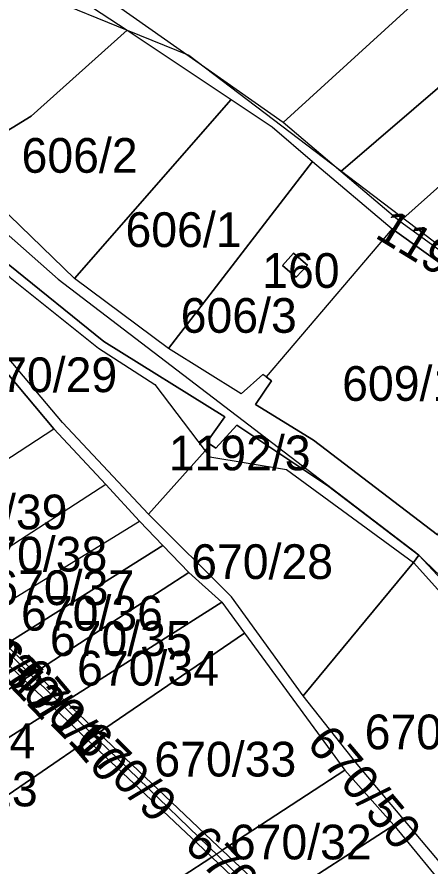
# Model space of a CAD drawing. Extents: x -623250 to -619626, y -1079612 to -1075424.
# Drawn here: x -620248 to -620128.9, y -1076980.5 to -1076735.9 of the extents above; entities that cross this region are included whole.
import ezdxf

# ---------------------------------------------------------------- set-up
doc = ezdxf.new("R2010")
doc.units = 0
for name, color, linetype in [('Cestní síť', 7, 'Continuous'), ('Hranice šetřená (k_ú_Džbánov - vnitřní obvod)', 7, 'Continuous'), ('Parcela nároku', 7, 'Continuous'), ('Parcelní číslo', 7, 'Continuous'), ('Vodní toky', 7, 'Continuous'), ('Železnice', 7, 'Continuous')]:
    doc.layers.add(name, color=color, linetype=linetype)

msp = doc.modelspace()

# ---------------------------------------------------------------- linework, layer by layer
at = {"layer": 'Cestní síť'}
for p, q in [((-620243.09, -1076728.76), (-620216.21, -1076739.68)), ((-620216.21, -1076739.68), (-620198.39, -1076746.92)), ((-620198.39, -1076746.92), (-620118.57, -1076807.57))]:
    msp.add_line(p, q, dxfattribs=at)
at = {"layer": 'Hranice šetřená (k_ú_Džbánov - vnitřní obvod)'}
msp.add_lwpolyline([(-620126.72, -1076885.06), (-620162.51, -1076857.82), (-620179.17, -1076847.51), (-620174.58, -1076840.72), (-620176.18, -1076839.56), (-620177.1, -1076838.89), (-620183.39, -1076844.49), (-620204.25, -1076831.43), (-620231.38, -1076811.27), (-620265.87, -1076777.93), (-620243.92, -1076764.46), (-620216.21, -1076739.68), (-620186.23, -1076759.67), (-620174.43, -1076767.54), (-620162.81, -1076777.54), (-620139.82, -1076796.98), (-620090.81, -1076832)], dxfattribs=at)
at = {"layer": 'Parcela nároku'}
for points in [[(-620218.95, -1076732.82), (-620133.42, -1076663.2), (-620055.39, -1076602.7), (-620048.24, -1076609.49), (-620020.15, -1076639.93), (-620076.81, -1076680.16), (-620171.2, -1076766.27)], [(-620020.15, -1076639.93), (-620003.71, -1076657.74), (-620060.3, -1076699.43), (-620154.59, -1076780.38), (-620171.2, -1076766.27), (-620076.81, -1076680.16)], [(-620339.92, -1076659.27), (-620312.36, -1076646.89), (-620300.95, -1076664.9), (-620270.28, -1076698.89), (-620243.95, -1076721.47), (-620216.21, -1076739.68), (-620243.92, -1076764.46), (-620265.87, -1076777.93)], [(-620000.43, -1076661.3), (-619990.26, -1076676.62), (-620096.14, -1076757.87), (-620137.63, -1076794.79), (-620154.59, -1076780.38), (-620060.3, -1076699.43), (-620003.71, -1076657.74)], [(-619990.26, -1076676.62), (-619970, -1076709.39), (-620052.58, -1076768.37), (-620109.41, -1076815.23), (-620137.63, -1076794.79), (-620096.14, -1076757.87)], [(-620265.87, -1076777.93), (-620243.92, -1076764.46), (-620216.21, -1076739.68), (-620186.23, -1076759.67), (-620231.38, -1076811.27)], [(-620186.23, -1076759.67), (-620174.43, -1076767.54), (-620162.81, -1076777.54), (-620204.25, -1076831.43), (-620231.38, -1076811.27)], [(-620204.25, -1076831.43), (-620162.81, -1076777.54), (-620139.82, -1076796.98), (-620176.18, -1076839.56), (-620177.1, -1076838.89), (-620183.39, -1076844.49)], [(-620273.43, -1076782.45), (-620282.82, -1076788.66), (-620281.18, -1076791.72), (-620263.12, -1076797.79), (-620249.92, -1076810.99), (-620224.49, -1076831.34), (-620208.19, -1076841.81), (-620193.73, -1076860.85), (-620192.19, -1076859.04), (-620193.2, -1076858.34), (-620188.02, -1076851.09), (-620222.96, -1076829.38), (-620250.49, -1076807.09)], [(-620208.19, -1076841.81), (-620193.73, -1076860.85), (-620210.08, -1076879.13), (-620234.82, -1076852.68), (-620272.81, -1076807.82), (-620281.18, -1076791.72), (-620263.12, -1076797.79), (-620249.92, -1076810.99), (-620224.49, -1076831.34)], [(-620090.81, -1076832), (-620139.82, -1076796.98), (-620176.18, -1076839.56), (-620174.58, -1076840.72), (-620179.17, -1076847.51), (-620162.51, -1076857.82), (-620126.72, -1076885.06)], [(-620171.47, -1076807.45), (-620168.26, -1076803.98), (-620167.47, -1076804.65), (-620164.24, -1076807.4), (-620167.45, -1076810.87), (-620170.68, -1076808.12)], [(-620170.68, -1076808.12), (-620167.45, -1076810.87), (-620164.24, -1076807.4), (-620167.47, -1076804.65), (-620168.26, -1076803.98), (-620171.47, -1076807.45)], [(-620250.84, -1076838.48), (-620298.85, -1076869.96), (-620295.03, -1076874.95), (-620284.35, -1076885.13), (-620237.34, -1076854.52)], [(-620158.11, -1076871.1), (-620184.57, -1076853.48), (-620190.64, -1076860.12), (-620192.19, -1076859.04), (-620193.73, -1076860.85), (-620192.38, -1076862.62), (-620170.3, -1076866.27), (-620133.69, -1076893.08), (-620132.13, -1076890.89)], [(-620237.34, -1076854.52), (-620222.38, -1076870.61), (-620268.42, -1076900.3), (-620284.35, -1076885.13)], [(-620193.73, -1076860.85), (-620192.38, -1076862.62), (-620170.3, -1076866.27), (-620133.69, -1076893.08), (-620165.48, -1076931.43), (-620186.12, -1076902.91), (-620210.08, -1076879.13)], [(-620222.38, -1076870.61), (-620268.42, -1076900.3), (-620258.84, -1076909.43), (-620212.62, -1076881.11)], [(-620258.84, -1076909.43), (-620212.62, -1076881.11), (-620205.93, -1076888.11), (-620251.31, -1076916.61)], [(-620205.93, -1076888.11), (-620198.43, -1076895.95), (-620242.81, -1076924.7), (-620251.31, -1076916.61)], [(-620089.08, -1076954.75), (-620087.1, -1076957.24), (-620119.98, -1076986.55), (-620149.91, -1076951.14), (-620165.48, -1076931.43), (-620133.69, -1076893.08), (-620092.76, -1076938.48)], [(-620132.13, -1076890.89), (-620133.69, -1076893.08), (-620092.76, -1076938.48), (-620089.08, -1076954.75), (-620087.1, -1076957.24), (-620084.6, -1076955.01), (-620085.57, -1076953.89), (-620079.82, -1076946.92)], [(-620198.43, -1076895.95), (-620188.91, -1076904.44), (-620234.01, -1076933.05), (-620242.81, -1076924.7)], [(-620188.91, -1076904.44), (-620182.36, -1076913.38), (-620224.46, -1076942.1), (-620234.01, -1076933.05)], [(-620182.36, -1076913.38), (-620153.45, -1076952.88), (-620188.81, -1076975.92), (-620189.97, -1076974.83), (-620224.46, -1076942.1)], [(-620242.81, -1076924.7), (-620251.31, -1076916.61), (-620254.59, -1076918.67), (-620245.98, -1076926.75)], [(-620287.71, -1076939.79), (-620254.59, -1076918.67), (-620245.98, -1076926.75), (-620281.35, -1076949.67)], [(-620234.01, -1076933.05), (-620242.81, -1076924.7), (-620245.98, -1076926.75), (-620237.17, -1076935.05)], [(-620281.35, -1076949.67), (-620245.98, -1076926.75), (-620237.17, -1076935.05), (-620275.25, -1076959.21)], [(-620224.46, -1076942.1), (-620234.01, -1076933.05), (-620237.17, -1076935.05), (-620227.5, -1076944.17)], [(-620237.17, -1076935.05), (-620227.5, -1076944.17), (-620267.16, -1076971.23), (-620268.09, -1076967.66), (-620275.25, -1076959.21)], [(-620192.55, -1076977.12), (-620191.78, -1076977.86), (-620243.08, -1077011.3), (-620265.18, -1076975.21), (-620267.16, -1076971.23), (-620227.5, -1076944.17)], [(-620188.81, -1076975.92), (-620189.97, -1076974.83), (-620224.46, -1076942.1), (-620227.5, -1076944.17), (-620192.55, -1076977.12), (-620191.78, -1076977.86)], [(-620188.81, -1076975.92), (-620153.45, -1076952.88), (-620139.36, -1076968.66), (-620173.21, -1076990.56)], [(-620173.21, -1076990.56), (-620139.36, -1076968.66), (-620122.17, -1076989.65), (-620096.52, -1077018.79), (-620097.72, -1077022.14), (-620123.12, -1077037.77), (-620125.94, -1077034.91)], [(-620191.78, -1076977.86), (-620188.81, -1076975.92), (-620173.21, -1076990.56), (-620176.37, -1076992.61)], [(-620191.78, -1076977.86), (-620176.37, -1076992.61), (-620226, -1077024.71), (-620232.57, -1077028.92), (-620243.08, -1077011.3)]]:
    msp.add_lwpolyline(points, close=True, dxfattribs=at)
for points in [[(-620126.72, -1076885.06), (-620162.51, -1076857.82), (-620179.17, -1076847.51), (-620174.58, -1076840.72), (-620176.18, -1076839.56), (-620177.1, -1076838.89), (-620183.39, -1076844.49), (-620204.25, -1076831.43), (-620231.38, -1076811.27), (-620265.87, -1076777.93), (-620339.92, -1076659.27)], [(-620332.84, -1076687.58), (-620297.6, -1076749.85), (-620287.81, -1076772.52), (-620282.82, -1076788.66), (-620273.43, -1076782.45), (-620250.49, -1076807.09), (-620222.96, -1076829.38), (-620188.02, -1076851.09), (-620193.2, -1076858.34), (-620192.19, -1076859.04), (-620190.64, -1076860.12), (-620184.57, -1076853.48), (-620158.11, -1076871.1), (-620132.13, -1076890.89), (-620079.82, -1076946.92)], [(-620243.95, -1076721.47), (-620216.21, -1076739.68), (-620186.23, -1076759.67), (-620174.43, -1076767.54), (-620162.81, -1076777.54), (-620139.82, -1076796.98), (-620090.81, -1076832)], [(-620109.41, -1076815.23), (-620137.63, -1076794.79), (-620154.59, -1076780.38), (-620171.2, -1076766.27), (-620218.95, -1076732.82)], [(-620119.98, -1076986.55), (-620149.91, -1076951.14), (-620165.48, -1076931.43), (-620186.12, -1076902.91), (-620210.08, -1076879.13), (-620234.82, -1076852.68), (-620272.81, -1076807.82), (-620281.18, -1076791.72), (-620287.52, -1076789.59), (-620286.26, -1076791.95), (-620275.61, -1076809.03), (-620263.77, -1076823.1), (-620250.84, -1076838.48), (-620237.34, -1076854.52), (-620222.38, -1076870.61), (-620212.62, -1076881.11), (-620205.93, -1076888.11), (-620198.43, -1076895.95), (-620188.91, -1076904.44), (-620182.36, -1076913.38), (-620153.45, -1076952.88), (-620139.36, -1076968.66), (-620122.17, -1076989.65)]]:
    msp.add_lwpolyline(points, dxfattribs=at)
at = {"layer": 'Vodní toky'}
msp.add_line((-620301.87, -1076869.58), (-620113.61, -1077051.07), dxfattribs=at)
at = {"layer": 'Železnice'}
for p, q in [((-620259.43, -1076790.85), (-620236.14, -1076811.46)), ((-620236.14, -1076811.46), (-620133.14, -1076890.02)), ((-620133.14, -1076890.02), (-620088.06, -1076933.34))]:
    msp.add_line(p, q, dxfattribs=at)

# ---------------------------------------------------------------- texts
at = {"layer": 'Parcelní číslo'}
for s, p in [('606/2', (-620246.65, -1076780.79)), ('606/1', (-620216.69, -1076802.17)), ('160', (-620177.28, -1076813.94)), ('606/3', (-620200.77, -1076826.88)), ('670/29', (-620259.97, -1076843.97)), ('609/1', (-620154.24, -1076846.48)), ('1192/3', (-620204.23, -1076866.48)), ('670/39', (-620274.31, -1076883.48)), ('670/38', (-620262.83, -1076895.63)), ('670/28', (-620197.76, -1076897.79)), ('670/37', (-620255.07, -1076905.3)), ('670/36', (-620246.8, -1076912.66)), ('670/35', (-620238.49, -1076919.93)), ('670/34', (-620230.65, -1076928.49)), ('670/27', (-620147.74, -1076946.83)), ('765/14', (-620283.56, -1076949.4)), ('670/33', (-620208.36, -1076954.67)), ('765/13', (-620282.9, -1076963.27)), ('670/32', (-620186.61, -1076978.54))]:
    msp.add_text(s, height=10, dxfattribs=at).set_placement(p)
for s, rotation, p in [('1191', 328.6031, (-620145.13, -1076799.26)), ('670/13', 317.6301, (-620277.68, -1076903)), ('670/12', 313.8387, (-620268.68, -1076909.48)), ('670/11', 315, (-620257.35, -1076920.83)), ('670/10', 310.2001, (-620249.2, -1076925.87)), ('670/9', 315, (-620231.77, -1076944.96)), ('670/50', 310.1952, (-620164.79, -1076945.31)), ('670/8', 314.1231, (-620200.19, -1076974.68))]:
    msp.add_text(s, height=10, rotation=rotation, dxfattribs=at).set_placement(p)

doc.saveas('drawing.dxf')
